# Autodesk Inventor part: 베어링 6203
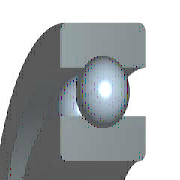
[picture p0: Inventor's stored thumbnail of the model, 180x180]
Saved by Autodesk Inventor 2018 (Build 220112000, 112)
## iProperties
IsCustomPart: 1
Created: 2015-09
Part Number: 베어링 6203
Material: 강철, 연강
Description: 깊은 그루브 볼 베어링
Document SubType Name: Modeling
Standard: KS B 2023
Standards Organization: KS
Language: ko-KR
Size Designation: 6203 - 17 x 40 x 12
Categories: <MemberInstance><Categories><Category DisplayName="샤프트 부품" InternalName="7f7aeb1f-a693-4053-b835-cee3144e0d98" Mnemonic="SHFT"><Category DisplayName="베어링" Inter
Density: 7.86 g/cm^3
Mass: 64.9809 g
Surface Area: 64.3582 cm^2
Volume: 8.26729 cm^3
Appearance: 노란색
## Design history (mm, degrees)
sketch "스케치" dims "d0" = 5.98 (= -0.26 x WD + 0.26 x BD)
  geometry: L1 (3.01, 14.25)-(8.99, 14.25); L2 (6, 14.25)-(6, 11.26); L3 (6, 14.25)-(6, 17.24); L4 (3.778, 12.249)-(0, 12.249); L5 (0, 8.5)-(12, 8.5); L6 (3.778, 16.251)-(0, 16.251); L7 (0, 20)-(12, 20); L8 (12, 8.5)-(12, 12.249); L9 (8.222, 12.249)-(12, 12.249); L10 (8.222, 16.251)-(12, 16.251); L11 (12, 20)-(12, 16.251); L12 (-1.4, 0)-(8.4, 0) reference; L13 (0, -0.3)-(0, 5.3) reference
  constraints: 22 end point, 4 point on line, 2 collinear, 2 perpendicular, 2 symmetric about line, 1 midpoint, 1 parallel, 14 other
  dimensions: "d9" = 17 diameter of L5 L12 (= WD); "d11" = 40 diameter of L7 L12 (= BD); "d12" = 12 distance between parallel lines of L8 L13 (= KB); "d13" = 24.498 diameter of L9 L12 (= 0.326 x BD + 0.674 x WD)
revolve "본체" stored, may be unused: angle "d6" = 90 deg
revolve "볼" stored, may be unused: angle "d7" = 90 deg
pattern_circular "IDS_ARRAYBALL[SIMPL:T]" dims angle "d3" = 360 deg
body "Solid1"
fillet "모깎기1" dims "d1" = 0.6 (= KRS)
other parameters: "WD" = 17 [user parameter; used in 5 equation terms], "BD" = 40 [user parameter; used in 5 equation terms], "KB" = 12 [user parameter; used in 1 equation term], "KRS" = 0.6 [user parameter; used in 1 equation term], "d4" = 0, "d5" = 0, "d8" = 0, "d14" = 0, "d15" = 0, "BBA" = 0 [user parameter], "BC0" = 4750000 [user parameter], "BC" = 9560000 [user parameter], "WR" = 8.5 (= 0.5 x WD) [user parameter]
